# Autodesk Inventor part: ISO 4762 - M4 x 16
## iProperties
Comments: To add or edit properties for Autodesk Inventor files, use iProperties.
Created: 2004-08
Part Number: ISO 4762 - M4 x 16
Vendor: Autodesk Inc.
Document SubType Name: Modeling
Designer: John Blackburn
Material: Default
Description: Hexagon Socket Head Cap Screw
Standard: ISO 4762
Size Designation: M4 x 16
Alert: To add or edit properties for Autodesk Inventor files, use iProperties.
Control State: 0
Master: False
Checked Out: False
Shininess: 64.0
Length Units: 11269
Angle Units: 11279
Time Units: 11290
Mass Units: 11283
Length Display Precision: 3
Angle Display Precision: 2
Compacted: True
EGR: 1
Density: 0.0
Volumn: 0.0
Area: 0.0
PropertySet Name: Model Information
Author: John Blackburn
Revision Number: 8
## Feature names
1. Body [Revolution]
2. Slot [Extrusion]
3. Fillet1
4. Chamfer1
